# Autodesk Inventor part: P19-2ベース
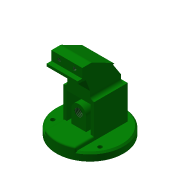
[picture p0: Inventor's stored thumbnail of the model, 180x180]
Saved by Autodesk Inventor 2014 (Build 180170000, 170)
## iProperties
Created: 2008-07
Part Number: P19-2ベース
Document SubType Name: Modeling
Designer: y-shimohigashi
Density: 1 g/cm^3
Stock Number: P19-2ベース
Material: 一般
Appearance: 濃い緑
Author: y-shimohigashi
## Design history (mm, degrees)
sketch "スケッチ2"
  geometry: C1 r 65 at (0, 0); 1 further point
  constraints: 1 centre point, 1 coincident
  dimensions: "d0" = 130 diameter of C1
extrude "押し出し1" new body sketch "スケッチ2" distance "d1" = 15; taper "d2" = 0 deg
sketch "スケッチ3"
  geometry: L1 (-65, 15)-(65, 15) reference; L2 (43, 15)-(43, 80); L3 (43, 80)-(38, 80); L4 (38, 80)-(38, 93); L5 (38, 93)-(16, 127); L6 (16, 127)-(-27, 149); L7 (-27, 149)-(-45, 149); L8 (-45, 149)-(-45, 131); L9 (-45, 131)-(-54, 131); L10 (-54, 131)-(-54, 126); L11 (-54, 126)-(-44, 126); L12 (-44, 126)-(-31, 119); L13 (-31, 119)-(-22, 95); L14 (-22, 95)-(-22, 15); L15 (-22, 15)-(43, 15); 1 further point
  constraints: 28 end point, 6 parallel, 3 perpendicular, 2 point on line, 1 collinear
  dimensions: "d3" = 43 distance from line of L2 point (0, 0); "d4" = 65 distance of L2.start L2.end; "d5" = 13 distance of L3.end L4.end; "d6" = 34 vertical distance of L4.end L5.end; "d7" = 22 vertical distance of L5.end L6.end; "d8" = 5 distance of L2.end L3.end; "d9" = 22 horizontal distance of L4.end L5.end; "d10" = 43 horizontal distance of L5.end L6.end; "d11" = 18 distance of L6.end L7.end; "d12" = 9 distance of L8.end L9.end; "d13" = 18 distance of L7.end L8.end; "d14" = 5 distance of L9.end L10.end; "d15" = 10 distance of L10.end L11.end; "d16" = 24 vertical distance of L12.end L13.end; "d17" = 80 distance of L13.end L14.end; "d18" = 65 distance between parallel lines of L2 L14; "d19" = 13 horizontal distance of L11.end L12.end
extrude "押し出し2" join sketch "スケッチ3" stored distance "d20" = 60; taper "d21" = 0 deg
sketch "スケッチ4"
  geometry: L1 (0, 0)-(60, 0) reference; L2 (60, 0)-(52, 0); L3 (52, 0)-(52, -45); L4 (52, -45)-(60, -45); L5 (60, -45)-(60, 0); L6 (0, 0)-(8, 0); L7 (8, 0)-(8, -45); L8 (8, -45)-(0, -45); L9 (0, -45)-(0, 0)
  constraints: 16 end point, 4 parallel, 2 collinear, 2 horizontal, 2 perpendicular
  dimensions: "d22" = 8 distance of L3.end L4.end; "d23" = 45 distance of L4.end L1.end
extrude "押し出し3" cut sketch "スケッチ4" stored distance "d24" = 60; taper "d25" = 0 deg
sketch "スケッチ5"
  geometry: L1 (60, -65)-(60, 0) reference; L2 (0, 0)-(60, 0) reference; L3 (0, 0)-(0, -65) reference; L4 (0, -65)-(60, -65) reference; L5 (53, -58)-(53, -7); L6 (53, -7)-(7, -7); L7 (7, -7)-(7, -58); L8 (7, -58)-(53, -58); L9 (44.5, -7)-(44.5, -32.5); L10 (15.5, -32.5)-(15.5, -7); A1 r 14.5 centre (30, -32.5) between (15.5, -32.5) and (44.5, -32.5); 2 further points
  constraints: 12 end point, 2 midpoint, 2 perpendicular, 2 point on circle, 2 point on line, 2 tangent, 1 centre point, 1 horizontal alignment, 1 vertical alignment, 3 other
  dimensions: "d26" = 7 distance between parallel lines of L3 L7; "d27" = 8.5 distance between parallel lines of L7 L10
extrude "押し出し4" cut sketch "スケッチ5" stored distance "d28" = 60; taper "d29" = 0 deg
hole "穴1" diameter "d32" = 15.294; stored, may be unused: countersink angle "d36" = 90 deg, drill point angle "d38" = 118 deg; dims "d30" = 10, "d31" = 10, "d33" = 6, "d34" = 4, "d35" = 2, "d37" = 8
sketch "スケッチ6"
  geometry: L1 (30, -22)-(-30, -22) reference; L2 (-30, -22)-(-30, -57.663); L3 (30, -22)-(30, -57.663); A1 r 65 centre (0, 0) between (-30, -57.663) and (30, -57.663) reference; A2 r 65 centre (0, 0) between (-30, -57.663) and (30, -57.663)
  constraints: 4 end point, 4 point on circle, 1 centre point, 1 concentric, 1 parallel, 1 perpendicular
extrude "押し出し5" join sketch "スケッチ6" stored distance "d39" = 60; taper "d40" = 0 deg
sketch "スケッチ7" dims "d41" = 106
  geometry: 3 further points
  constraints: 2 vertical alignment, 1 coincident, 2 other
hole "穴2" sketch "スケッチ7" at (0, 53) diameter "d42" = 8; stored, may be unused: countersink angle "d46" = 90 deg, drill point angle "d48" = 118 deg; dims "d43" = 6, "d44" = 4, "d45" = 2, "d47" = 8
pattern_circular "放射状パターン1" dims angle "d50" = 360 deg
sketch "スケッチ8"
  geometry: L1 (30, -178.8)-(30, 29.8) reference; L2 (60, -18)-(60, 0) reference; 3 further points
  constraints: 1 horizontal alignment, 1 midpoint, 1 symmetric about line
  dimensions: "d53" = 30 distance of point (15, -9) point (45, -9)
hole "穴3" sketch "スケッチ8" at (15, -9), (45, -9) diameter "d54" = 6.647; stored, may be unused: countersink angle "d58" = 90 deg, drill point angle "d60" = 118 deg; dims "d55" = 6, "d56" = 4, "d57" = 2, "d59" = 8
fillet "フィレット1" dims "d52" = 8
fillet "フィレット2" dims "d61" = 8
fillet "フィレット3" dims "d62" = 3
chamfer "面取り1" distance "d63" = 3; stored, may be unused: second distance "d64" = 2, angle "d65" = 45 deg
node "ソリッド1"
node "ソリッド ボディ"
node "サーフェス ボディ"
node "投影ループ1"
